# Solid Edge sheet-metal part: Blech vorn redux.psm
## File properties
Author: heha
Template: Normal.psm
Last saved by: heha
Revision: 17
Application: Solid Edge
Materialstärke: 1,50 mm
Biegeradius: 1,50 mm
Ausklinkungsbreite: 1,50 mm
Ausklinkungslänge: 1,50 mm
Neutralfaktor: 0,330
Dichte: 2,712 kg/dm^3
Genauigkeit: 0,99
Minimale Bogenlänge: 0,10 mm
Abweichungstoleranz: 0,10 mm
Material: Aluminium, 1060
Teilflächenformatvorlage: Aluminium
Füllformatvorlage: ANSI38(Aluminum)
Virtuelle Formatvorlage: Poliertes Aluminium
Coef. of Thermal Exp: 2.3e-05
Thermal Conductivity: 221.0
Specific Heat: 920.0
Modulus of Elasticity: 68947570000.0
Poission's Ratio: 0.33
Yield Stress: 27579028.0
Ultimate Stress: 68947570.0
Elongation: 0.0
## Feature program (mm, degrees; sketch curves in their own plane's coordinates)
base tab "unnamed BaseTab 1"
sheet metal cutout "unnamed SheetMetalCutout 1"
sheet metal cutout "unnamed SheetMetalCutout 2"
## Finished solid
Body 1: solid body, 26 faces, 68 edges, 40 vertices.
  Faces by surface: cylinder 14, plane 12
  Edges by curve: line 40, circle 28
Bounding box of the edges (mm): 103.000 x 1.500 x 56.000, from (-51.5, -1.5, -28) to (51.5, 0, 28).
Cylindrical faces by radius (mm): R1.6 x4, R2 x4, R6.4 x6
Planar faces by outward normal: +x 1, +y 1, +z 3, -x 1, -y 1, -z 5
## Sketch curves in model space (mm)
circle centre (-38.1, 0, -12.4) radius 6.4
circle centre (-12.7, 0, -12.4) radius 6.4
circle centre (38.1, 0, -12.4) radius 6.4
circle centre (12.7, 0, -12.4) radius 6.4
circle centre (38.1, 0, 12.4) radius 6.4
circle centre (12.7, 0, 12.4) radius 6.4
line (49.5, 0, 21.2) -> (49.5, 0, 19.4)
line (49.5, 0, 19.4) -> (-49.5, 0, 19.4)
line (-49.5, 0, 19.4) -> (-49.5, 0, 21.2)
line (-49.5, 0, 21.2) -> (49.5, 0, 21.2)
line (49.5, 0, -19.4) -> (49.5, 0, -21.2)
line (49.5, 0, -21.2) -> (-49.5, 0, -21.2)
line (-49.5, 0, -21.2) -> (-49.5, 0, -19.4)
line (-49.5, 0, -19.4) -> (49.5, 0, -19.4)
line (-45.4, 0, -6.9) -> (-30.8, 0, -6.9)
line (-30.8, 0, -6.9) -> (-30.8, 0, -19.4)
line (-30.8, 0, -19.4) -> (-45.4, 0, -19.4)
line (-45.4, 0, -19.4) -> (-45.4, 0, -6.9)
line (-20, 0, -6.9) -> (-5.4, 0, -6.9)
line (-5.4, 0, -6.9) -> (-5.4, 0, -19.4)
line (-5.4, 0, -19.4) -> (-20, 0, -19.4)
line (-20, 0, -19.4) -> (-20, 0, -6.9)
line (5.4, 0, -6.9) -> (20, 0, -6.9)
line (20, 0, -6.9) -> (20, 0, -19.4)
line (20, 0, -19.4) -> (5.4, 0, -19.4)
line (5.4, 0, -19.4) -> (5.4, 0, -6.9)
line (30.8, 0, -19.4) -> (45.4, 0, -19.4)
line (45.4, 0, -19.4) -> (45.4, 0, -6.9)
line (45.4, 0, -6.9) -> (30.8, 0, -6.9)
line (30.8, 0, -6.9) -> (30.8, 0, -19.4)
line (5.4, 0, 19.4) -> (20, 0, 19.4)
line (20, 0, 19.4) -> (20, 0, 6.9)
line (20, 0, 6.9) -> (5.4, 0, 6.9)
line (5.4, 0, 6.9) -> (5.4, 0, 19.4)
line (30.8, 0, 19.4) -> (45.4, 0, 19.4)
line (45.4, 0, 19.4) -> (45.4, 0, 6.9)
line (45.4, 0, 6.9) -> (30.8, 0, 6.9)
line (30.8, 0, 6.9) -> (30.8, 0, 19.4)
circle centre (-47.5, 0, -24) radius 1.3
line (-41.5, 0, -27) -> (0, 0, -27)
line (-41.5, 0, -25.2) -> (0, 0, -25.2)
line (-41.5, 0, -28) -> (-41.5, 0, -27)
line (-49.5, 0, -28) -> (-41.5, 0, -28)
arc centre (-49.5, 0, -26) radius 2 from (-51.5, 0, -26) through (-50.8725, 0, -27.4547) to (-49.5, 0, -28)
line (-51.5, 0, 26) -> (-51.5, 0, -26)
arc centre (-49.5, 0, 26) radius 2 from (-49.5, 0, 28) through (-50.9547, 0, 27.3725) to (-51.5, 0, 26)
line (-41.5, 0, 28) -> (-49.5, 0, 28)
line (-44.5, 0, -25.2) -> (-41.5, 0, -25.2)
line (-44.5, 0, -27) -> (-44.5, 0, -25.2)
line (-41.5, 0, -27) -> (-44.5, 0, -27)
line (-47.5, 0, 0.9) -> (-47.5, 0, 2)
line (-49.5, 0, 0.9) -> (-47.5, 0, 0.9)
line (-49.5, 0, -0.9) -> (-49.5, 0, 0.9)
line (-47.5, 0, -0.9) -> (-49.5, 0, -0.9)
line (-47.5, 0, -2) -> (-47.5, 0, -0.9)
line (-49.5, 0, -2) -> (-47.5, 0, -2)
line (-49.5, 0, -3.8) -> (-49.5, 0, -2)
line (-47.5, 0, -3.8) -> (-49.5, 0, -3.8)
line (-47.5, 0, -4.9) -> (-47.5, 0, -3.8)
line (-49.5, 0, -4.9) -> (-47.5, 0, -4.9)
line (-49.5, 0, -6.7) -> (-49.5, 0, -4.9)
line (-47.5, 0, -6.7) -> (-49.5, 0, -6.7)
line (-47.5, 0, -7.8) -> (-47.5, 0, -6.7)
line (-49.5, 0, -7.8) -> (-47.5, 0, -7.8)
line (-49.5, 0, -9.6) -> (-49.5, 0, -7.8)
line (-47.5, 0, -9.6) -> (-49.5, 0, -9.6)
line (-47.5, 0, -10.7) -> (-47.5, 0, -9.6)
line (-49.5, 0, -10.7) -> (-47.5, 0, -10.7)
line (-49.5, 0, -12.5) -> (-49.5, 0, -10.7)
line (-47.5, 0, -12.5) -> (-49.5, 0, -12.5)
line (-47.5, 0, -13.6) -> (-47.5, 0, -12.5)
line (-49.5, 0, -13.6) -> (-47.5, 0, -13.6)
line (-49.5, 0, -15.4) -> (-49.5, 0, -13.6)
line (-47.5, 0, -15.4) -> (-49.5, 0, -15.4)
line (-47.5, 0, -16.5) -> (-47.5, 0, -15.4)
line (-49.5, 0, -16.5) -> (-47.5, 0, -16.5)
line (-49.5, 0, -18.3) -> (-49.5, 0, -16.5)
line (-47.5, 0, -18.3) -> (-49.5, 0, -18.3)
line (-47.5, 0, -19.4) -> (-47.5, 0, -18.3)
line (-49.5, 0, -19.4) -> (-47.5, 0, -19.4)
line (-49.5, 0, -21.2) -> (-49.5, 0, -19.4)
line (-46.9, 0, -21.2) -> (-49.5, 0, -21.2)
line (-46.9, 0, -22.8) -> (-46.9, 0, -21.2)
line (-41.5, 0, -22.8) -> (-46.9, 0, -22.8)
line (-41.5, 0, -25.2) -> (-41.5, 0, -22.8)
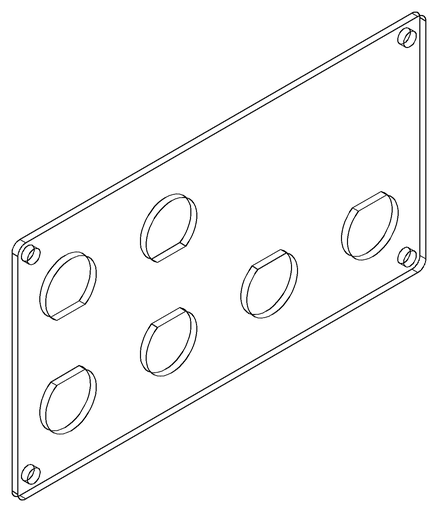
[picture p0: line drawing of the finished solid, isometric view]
